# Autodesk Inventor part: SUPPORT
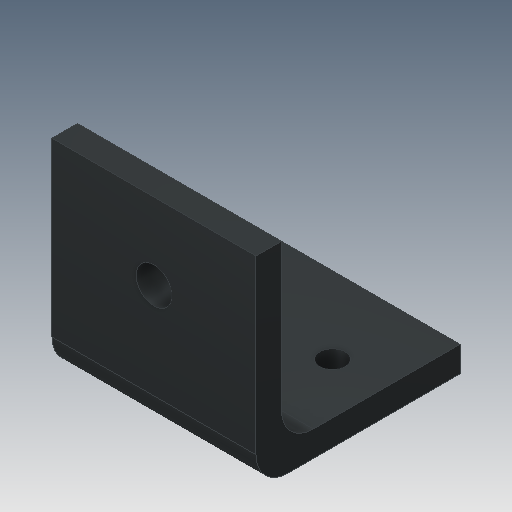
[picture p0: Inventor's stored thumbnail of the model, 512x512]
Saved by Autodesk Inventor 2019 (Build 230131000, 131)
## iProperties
Created: 2016-05
Part Number: SUPPORT
Material: Iron, Cast
Document SubType Name: Modeling
Designer: CADCIM
Density: 7.15 g/cm^3
Appearance: Iron Gray
Mass: 104.47 g
Surface Area: 70.4692 cm^2
Volume: 14.6112 cm^3
Author: CADCIM
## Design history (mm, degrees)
sketch "Sketch1"
  geometry: L1 (0, 0)-(40, 0); L2 (40, 0)-(40, -5); L3 (40, -5)-(5, -5); L4 (5, -5)-(5, -40); L5 (5, -40)-(0, -40); L6 (0, -40)-(0, 0)
  constraints: 12 end point, 2 parallel, 2 perpendicular, 1 horizontal
  dimensions: "d2" = 40 distance between parallel lines of L6 L2; "d3" = 40 distance of L5.end L1.start; "d4" = 5 distance between parallel lines of L1 L3
extrude "Extrusion1" new body sketch "Sketch1" distance "d0" = 40; taper "d1" = 0 deg
sketch "Sketch2"
  geometry: L1 (0, 0)-(0, 35) reference; L2 (0, 35)-(-40, 35) reference; C1 r 3.5 at (-20, 20); 1 further point
  constraints: 1 centre point
  dimensions: "d5" = 7 diameter of C1; "d6" = 20 distance from line of C1.centre L1; "d7" = 15 distance from line of L2 C1.centre
extrude "Extrusion2" cut sketch "Sketch2" distance "d8" = 40; taper "d9" = 0 deg
sketch "Sketch3"
  geometry: L1 (40, 35)-(40, 0) reference; L2 (0, 35)-(40, 35) reference; C1 r 2.5 at (10, 20); C2 r 2.5 at (30, 20); 1 further point
  constraints: 2 centre point, 1 equal radius, 1 horizontal alignment
  dimensions: "d10" = 20 distance of C2.centre C1.centre; "d11" = 10 distance from line of L1 C2.centre; "d12" = 15 distance from line of L2 C2.centre; "d13" = 5 diameter of C1
extrude "Extrusion3" cut sketch "Sketch3" distance "d14" = 40; taper "d15" = 0 deg
fillet "Fillet1" dims "d16" = 6.25
body "Solid1"
